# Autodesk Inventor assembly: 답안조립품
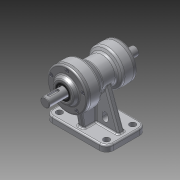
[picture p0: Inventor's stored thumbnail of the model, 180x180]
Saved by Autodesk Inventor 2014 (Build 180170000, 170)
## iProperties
Created: 2015-08
Part Number: 답안조립품
Document SubType Name: Assembly
Designer: Owner
Author: Owner
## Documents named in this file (10)
- C:\Documents and Settings\Owner\바탕 화면\450805V1010\답안조립품.iam
- C:\Documents and Settings\Owner\바탕 화면\450805V1010\본체.ipt
- C:\Documents and Settings\Owner\바탕 화면\450805V1010\축.ipt
- C:\Documents and Settings\Owner\바탕 화면\450805V1010\베어링 6205.ipt
- C:\Documents and Settings\Owner\바탕 화면\450805V1010\베어링 6203.ipt
- C:\Documents and Settings\Owner\바탕 화면\450805V1010\앞커버.ipt
- C:\Documents and Settings\Owner\바탕 화면\450805V1010\뒤커버.ipt
- C:\Documents and Settings\Owner\바탕 화면\450805V1010\오일실 .ipt
- 오일실 .ipt
- C:\Documents and Settings\Owner\바탕 화면\450805V1010\M4x0.5.ipt
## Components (10 placed, 1 different names)
1. M4x0.5:1
2. M4x0.5:2
3. M4x0.5:3
4. M4x0.5:4
5. M4x0.5:5
6. M4x0.5:6
7. M4x0.5:7
8. M4x0.5:8
9. M4x0.5:9
10. M4x0.5:10
